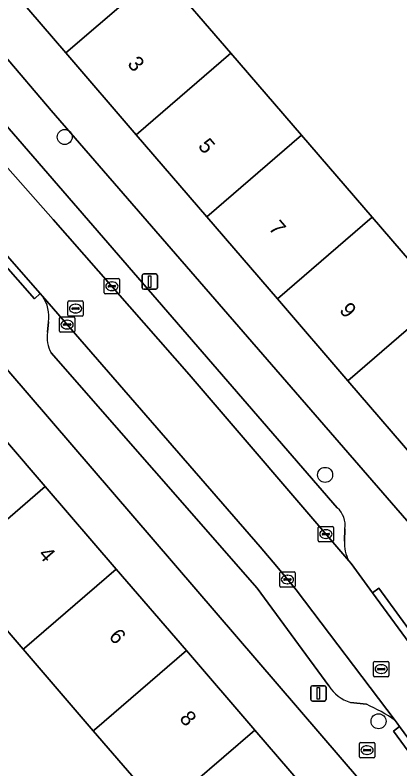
# Model space of a CAD drawing. Extents: x 162523 to 163266, y 381230 to 382050.
# Drawn here: x 162615.3 to 162640.34, y 381818.68 to 381867.74 of the extents above; entities that cross this region are included whole.
import ezdxf

# ---------------------------------------------------------------- set-up
doc = ezdxf.new("R2010")
doc.units = 0
for name, color, linetype in [('IMGEO_Boom', 7, 'Continuous'), ('IMGEO_Brandkraan', 7, 'Continuous'), ('IMGEO_Erf', 7, 'Continuous'), ('IMGEO_Kolk', 7, 'Continuous'), ('IMGEO_Lichtmast', 7, 'Continuous'), ('IMGEO_Pand', 7, 'Continuous'), ('IMGEO_Pand_nummerreeks', 7, 'Continuous'), ('IMGEO_Parkeervlak_open', 7, 'Continuous'), ('IMGEO_Rijbaan_lokaal_open', 7, 'Continuous'), ('IMGEO_Rioolput', 7, 'Continuous'), ('IMGEO_Voetpad_open', 7, 'Continuous')]:
    doc.layers.add(name, color=color, linetype=linetype)

msp = doc.modelspace()

# ---------------------------------------------------------------- linework, layer by layer
at = {"layer": 'IMGEO_Boom'}
for centre in [(162618.53, 381859.8), (162635.478, 381837.813), (162638.952, 381821.777)]:
    msp.add_circle(centre, 0.489, dxfattribs=at)
at = {"layer": 'IMGEO_Brandkraan'}
for p, q in [((162637.785, 381820.399), (162638.637, 381820.399)), ((162637.71, 381819.473), (162637.71, 381820.325)), ((162637.969, 381819.893), (162637.969, 381819.905)), ((162638.407, 381819.856), (162638.009, 381819.856)), ((162638.012, 381819.942), (162638.41, 381819.942)), ((162638.198, 381820.179), (162638.223, 381820.179)), ((162638.453, 381819.905), (162638.453, 381819.893)), ((162638.711, 381820.325), (162638.711, 381819.473)), ((162638.637, 381819.399), (162637.785, 381819.399)), ((162638.221, 381819.619), (162638.196, 381819.619))]:
    msp.add_line(p, q, dxfattribs=at)
for points in [[(162637.785, 381820.399), (162638.637, 381820.399)], [(162637.71, 381819.473), (162637.71, 381820.325)], [(162638.711, 381820.325), (162638.711, 381819.473)], [(162638.637, 381819.399), (162637.785, 381819.399)]]:
    msp.add_lwpolyline(points, dxfattribs=at)
for centre, radius, start, end in [((162637.787, 381820.323), 0.0765, 91.552, 178.448), ((162637.787, 381820.323), 0.0765, 91.552, 178.448), ((162638.635, 381820.323), 0.0765, 1.552, 88.448), ((162638.635, 381820.323), 0.0765, 1.552, 88.448), ((162638.009, 381819.902), 0.0403, 85.8775, 175.7526), ((162638.006, 381819.892), 0.0366, 178.938, 274.7102), ((162638.41, 381819.899), 0.043, 264.8664, 352.4533), ((162638.414, 381819.904), 0.0386, 1.7309, 96.639), ((162637.787, 381819.475), 0.0765, 181.552, 268.448), ((162637.787, 381819.475), 0.0765, 181.552, 268.448), ((162638.635, 381819.475), 0.0765, 271.552, 358.448), ((162638.635, 381819.475), 0.0765, 271.552, 358.448)]:
    msp.add_arc(centre, radius, start, end, dxfattribs=at)
for centre, major_axis, ratio, start_param, end_param in [((162638.197, 381819.899), (-0.387, 0.002), 0.722429, 4.712389, 7.853982), ((162638.222, 381819.899), (-0.39, 0.002), 0.717154, 1.570796, 4.712389)]:
    msp.add_ellipse(centre, major_axis=major_axis, ratio=ratio, start_param=start_param, end_param=end_param, dxfattribs=at)
at = {"layer": 'IMGEO_Erf'}
for points in [[(162608.447, 381872.351), (162617.656, 381861.527), (162641.079, 381834.52), (162645.193, 381837.891), (162645.564, 381838.195), (162651.746, 381843.259), (162654.733, 381845.707), (162655.225, 381846.11), (162652.994, 381848.812), (162648.983, 381853.709), (162649.512, 381854.143), (162647.831, 381856.195), (162645.254, 381859.341), (162647.405, 381861.103), (162649.938, 381858.01), (162651.663, 381855.904), (162655.674, 381851.007), (162656.106, 381851.292), (162641.659, 381868.486)], [(162624.758, 381870.581), (162629.348, 381865.247), (162633.94, 381859.912), (162638.532, 381854.575), (162642.976, 381849.413), (162643.125, 381849.24), (162646.224, 381851.908), (162648.431, 381849.344), (162645.33, 381846.676), (162647.663, 381843.965), (162648.065, 381843.499), (162647.74, 381843.22), (162647.361, 381843.661), (162643.626, 381840.446), (162641.872, 381838.937), (162642.27, 381838.474), (162641.918, 381838.171), (162636.961, 381843.931), (162632.368, 381849.268), (162627.776, 381854.603), (162623.185, 381859.939), (162618.592, 381865.275), (162613.633, 381871.038)], [(162637.769, 381817.908), (162613.536, 381846.073), (162608.946, 381841.96), (162607.949, 381841.067), (162606.255, 381839.549), (162604.298, 381841.733), (162605.992, 381843.251), (162606.989, 381844.144), (162606.643, 381844.53), (162611.397, 381848.79), (162607.795, 381852.831), (162606.311, 381854.495), (162602.884, 381851.424), (162601.7, 381850.363), (162597.214, 381846.343), (162592.736, 381842.329), (162588.257, 381838.316), (162583.779, 381834.303), (162579.309, 381830.297)], [(162615.822, 381826.466), (162611.203, 381831.833), (162606.117, 381837.742), (162606.445, 381838.024), (162606.802, 381837.609), (162608.744, 381839.28), (162612.249, 381842.296), (162611.907, 381842.694), (162612.192, 381842.939), (162617.262, 381837.048), (162621.883, 381831.678), (162626.444, 381826.379), (162630.902, 381821.198), (162635.455, 381815.908)], [(162624.843, 381815.984), (162620.382, 381821.167), (162615.822, 381826.466)]]:
    msp.add_lwpolyline(points, dxfattribs=at)
at = {"layer": 'IMGEO_Kolk'}
for p, q in [((162621.095, 381849.666), (162621.095, 381850.518)), ((162621.17, 381850.592), (162622.022, 381850.592)), ((162621.583, 381850.372), (162621.608, 381850.372)), ((162622.096, 381850.518), (162622.096, 381849.666)), ((162621.354, 381850.086), (162621.354, 381850.098)), ((162621.792, 381850.049), (162621.394, 381850.049)), ((162621.397, 381850.135), (162621.795, 381850.135)), ((162621.606, 381849.812), (162621.581, 381849.812)), ((162621.838, 381850.098), (162621.838, 381850.086)), ((162622.022, 381849.592), (162621.17, 381849.592)), ((162618.184, 381847.165), (162618.184, 381848.017)), ((162618.259, 381848.091), (162619.111, 381848.091)), ((162618.672, 381847.871), (162618.697, 381847.871)), ((162619.185, 381848.017), (162619.185, 381847.165)), ((162618.443, 381847.585), (162618.443, 381847.597)), ((162618.881, 381847.548), (162618.483, 381847.548)), ((162618.486, 381847.634), (162618.884, 381847.634)), ((162618.695, 381847.311), (162618.67, 381847.311)), ((162618.927, 381847.597), (162618.927, 381847.585)), ((162619.111, 381847.091), (162618.259, 381847.091)), ((162635.027, 381833.533), (162635.027, 381834.385)), ((162635.102, 381834.459), (162635.954, 381834.459)), ((162635.515, 381834.239), (162635.54, 381834.239)), ((162636.028, 381834.385), (162636.028, 381833.533)), ((162635.286, 381833.953), (162635.286, 381833.965)), ((162635.724, 381833.916), (162635.326, 381833.916)), ((162635.329, 381834.002), (162635.727, 381834.002)), ((162635.538, 381833.679), (162635.513, 381833.679)), ((162635.77, 381833.965), (162635.77, 381833.953)), ((162635.954, 381833.459), (162635.102, 381833.459)), ((162632.526, 381830.578), (162632.526, 381831.43)), ((162632.601, 381831.504), (162633.453, 381831.504)), ((162633.014, 381831.284), (162633.039, 381831.284)), ((162633.527, 381831.43), (162633.527, 381830.578)), ((162632.785, 381830.998), (162632.785, 381831.01)), ((162633.223, 381830.961), (162632.825, 381830.961)), ((162632.828, 381831.047), (162633.226, 381831.047)), ((162633.037, 381830.724), (162633.012, 381830.724)), ((162633.269, 381831.01), (162633.269, 381830.998)), ((162633.453, 381830.504), (162632.601, 381830.504))]:
    msp.add_line(p, q, dxfattribs=at)
for points in [[(162621.095, 381849.666), (162621.095, 381850.518)], [(162621.17, 381850.592), (162622.022, 381850.592)], [(162622.096, 381850.518), (162622.096, 381849.666)], [(162622.022, 381849.592), (162621.17, 381849.592)], [(162618.184, 381847.165), (162618.184, 381848.017)], [(162618.259, 381848.091), (162619.111, 381848.091)], [(162619.185, 381848.017), (162619.185, 381847.165)], [(162619.111, 381847.091), (162618.259, 381847.091)], [(162635.027, 381833.533), (162635.027, 381834.385)], [(162635.102, 381834.459), (162635.954, 381834.459)], [(162636.028, 381834.385), (162636.028, 381833.533)], [(162635.954, 381833.459), (162635.102, 381833.459)], [(162632.526, 381830.578), (162632.526, 381831.43)], [(162632.601, 381831.504), (162633.453, 381831.504)], [(162633.527, 381831.43), (162633.527, 381830.578)], [(162633.453, 381830.504), (162632.601, 381830.504)]]:
    msp.add_lwpolyline(points, dxfattribs=at)
for centre, radius, start, end in [((162621.172, 381850.516), 0.0765, 91.552, 178.448), ((162621.172, 381850.516), 0.0765, 91.552, 178.448), ((162622.02, 381850.516), 0.0765, 1.552, 88.448), ((162622.02, 381850.516), 0.0765, 1.552, 88.448), ((162621.394, 381850.095), 0.0403, 85.8775, 175.7526), ((162621.391, 381850.085), 0.0366, 178.938, 274.7102), ((162621.795, 381850.092), 0.043, 264.8664, 352.4533), ((162621.799, 381850.097), 0.0386, 1.7309, 96.639), ((162621.172, 381849.668), 0.0765, 181.552, 268.448), ((162621.172, 381849.668), 0.0765, 181.552, 268.448), ((162622.02, 381849.668), 0.0765, 271.552, 358.448), ((162622.02, 381849.668), 0.0765, 271.552, 358.448), ((162618.261, 381848.015), 0.0765, 91.552, 178.448), ((162618.261, 381848.015), 0.0765, 91.552, 178.448), ((162619.109, 381848.015), 0.0765, 1.552, 88.448), ((162619.109, 381848.015), 0.0765, 1.552, 88.448), ((162618.483, 381847.594), 0.0403, 85.8775, 175.7526), ((162618.48, 381847.584), 0.0366, 178.938, 274.7102), ((162618.884, 381847.591), 0.043, 264.8664, 352.4533), ((162618.888, 381847.596), 0.0386, 1.7309, 96.639), ((162618.261, 381847.167), 0.0765, 181.552, 268.448), ((162618.261, 381847.167), 0.0765, 181.552, 268.448), ((162619.109, 381847.167), 0.0765, 271.552, 358.448), ((162619.109, 381847.167), 0.0765, 271.552, 358.448), ((162635.104, 381834.383), 0.0765, 91.552, 178.448), ((162635.104, 381834.383), 0.0765, 91.552, 178.448), ((162635.952, 381834.383), 0.0765, 1.552, 88.448), ((162635.952, 381834.383), 0.0765, 1.552, 88.448), ((162635.326, 381833.962), 0.0403, 85.8775, 175.7526), ((162635.323, 381833.952), 0.0366, 178.938, 274.7102), ((162635.727, 381833.959), 0.043, 264.8664, 352.4533), ((162635.731, 381833.964), 0.0386, 1.7309, 96.639), ((162635.104, 381833.535), 0.0765, 181.552, 268.448), ((162635.104, 381833.535), 0.0765, 181.552, 268.448), ((162635.952, 381833.535), 0.0765, 271.552, 358.448), ((162635.952, 381833.535), 0.0765, 271.552, 358.448), ((162632.603, 381831.428), 0.0765, 91.552, 178.448), ((162632.603, 381831.428), 0.0765, 91.552, 178.448), ((162633.451, 381831.428), 0.0765, 1.552, 88.448), ((162633.451, 381831.428), 0.0765, 1.552, 88.448), ((162632.825, 381831.007), 0.0403, 85.8775, 175.7526), ((162632.822, 381830.997), 0.0366, 178.938, 274.7102), ((162633.226, 381831.004), 0.043, 264.8664, 352.4533), ((162633.23, 381831.009), 0.0386, 1.7309, 96.639), ((162632.603, 381830.58), 0.0765, 181.552, 268.448), ((162632.603, 381830.58), 0.0765, 181.552, 268.448), ((162633.451, 381830.58), 0.0765, 271.552, 358.448), ((162633.451, 381830.58), 0.0765, 271.552, 358.448)]:
    msp.add_arc(centre, radius, start, end, dxfattribs=at)
for centre, major_axis, ratio, start_param, end_param in [((162621.582, 381850.092), (-0.387, 0.002), 0.722429, 4.712389, 7.853982), ((162621.607, 381850.092), (-0.39, 0.002), 0.717154, 1.570796, 4.712389), ((162618.671, 381847.591), (-0.387, 0.002), 0.722429, 4.712389, 7.853982), ((162618.696, 381847.591), (-0.39, 0.002), 0.717154, 1.570796, 4.712389), ((162635.514, 381833.959), (-0.387, 0.002), 0.722429, 4.712389, 7.853982), ((162635.539, 381833.959), (-0.39, 0.002), 0.717154, 1.570796, 4.712389), ((162633.013, 381831.004), (-0.387, 0.002), 0.722429, 4.712389, 7.853982), ((162633.038, 381831.004), (-0.39, 0.002), 0.717154, 1.570796, 4.712389)]:
    msp.add_ellipse(centre, major_axis=major_axis, ratio=ratio, start_param=start_param, end_param=end_param, dxfattribs=at)
at = {"layer": 'IMGEO_Lichtmast'}
for p, q in [((162623.567, 381849.988), (162623.567, 381850.788)), ((162623.567, 381850.788), (162623.567, 381849.988)), ((162623.667, 381850.888), (162624.457, 381850.888)), ((162624.457, 381850.888), (162623.667, 381850.888)), ((162624.557, 381850.788), (162624.557, 381849.988)), ((162624.557, 381849.988), (162624.557, 381850.788)), ((162624.457, 381849.888), (162623.667, 381849.888)), ((162623.667, 381849.888), (162624.457, 381849.888)), ((162634.546, 381823.195), (162634.546, 381823.995)), ((162634.546, 381823.995), (162634.546, 381823.195)), ((162634.646, 381824.095), (162635.436, 381824.095)), ((162635.436, 381824.095), (162634.646, 381824.095)), ((162635.536, 381823.995), (162635.536, 381823.195)), ((162635.536, 381823.195), (162635.536, 381823.995)), ((162635.436, 381823.095), (162634.646, 381823.095)), ((162634.646, 381823.095), (162635.436, 381823.095))]:
    msp.add_line(p, q, dxfattribs=at)
for points in [[(162623.987, 381850.763), (162624.137, 381850.763), (162624.137, 381850.013), (162623.987, 381850.013), (162623.987, 381850.763)], [(162634.966, 381823.97), (162635.116, 381823.97), (162635.116, 381823.22), (162634.966, 381823.22), (162634.966, 381823.97)]]:
    msp.add_lwpolyline(points, dxfattribs=at)
for centre, start, end in [((162623.667, 381850.788), 90, 180), ((162623.667, 381850.788), 90, 180), ((162624.457, 381850.788), 0, 90), ((162624.457, 381850.788), 360, 90), ((162623.667, 381849.988), 180, 270), ((162623.667, 381849.988), 180, 270), ((162624.457, 381849.988), 270, 0), ((162624.457, 381849.988), 270, 0), ((162634.646, 381823.995), 90, 180), ((162634.646, 381823.995), 90, 180), ((162635.436, 381823.995), 0, 90), ((162635.436, 381823.995), 360, 90), ((162634.646, 381823.195), 180, 270), ((162634.646, 381823.195), 180, 270), ((162635.436, 381823.195), 270, 0), ((162635.436, 381823.195), 270, 0)]:
    msp.add_arc(centre, 0.1, start, end, dxfattribs=at)
at = {"layer": 'IMGEO_Pand'}
for points in [[(162620.098, 381875.995), (162619.79, 381876.353), (162619.382, 381876.003), (162619.691, 381875.644), (162614.191, 381870.91), (162613.89, 381871.259), (162613.633, 381871.038), (162618.592, 381865.275), (162624.758, 381870.581), (162622.482, 381873.226), (162625.435, 381875.769), (162623.052, 381878.537)], [(162623.185, 381859.939), (162629.348, 381865.247), (162624.758, 381870.581), (162618.592, 381865.275)], [(162627.776, 381854.603), (162633.94, 381859.912), (162629.348, 381865.247), (162623.185, 381859.939)], [(162627.776, 381854.603), (162632.368, 381849.268), (162638.532, 381854.575), (162633.94, 381859.912)], [(162638.532, 381854.575), (162632.368, 381849.268), (162636.961, 381843.931), (162643.125, 381849.24), (162642.976, 381849.413)], [(162647.663, 381843.965), (162645.33, 381846.676), (162648.431, 381849.344), (162646.224, 381851.908), (162643.125, 381849.24), (162636.961, 381843.931), (162641.918, 381838.171), (162642.27, 381838.474), (162641.872, 381838.937), (162643.626, 381840.446), (162647.361, 381843.661), (162647.74, 381843.22), (162648.065, 381843.499)], [(162611.203, 381831.833), (162617.262, 381837.048), (162612.192, 381842.939), (162611.907, 381842.694), (162612.249, 381842.296), (162608.744, 381839.28), (162606.802, 381837.609), (162606.445, 381838.024), (162606.117, 381837.742)], [(162621.883, 381831.678), (162617.262, 381837.048), (162611.203, 381831.833), (162615.822, 381826.466), (162615.918, 381826.544)], [(162621.883, 381831.678), (162615.918, 381826.544), (162615.822, 381826.466), (162620.382, 381821.167), (162620.463, 381821.232), (162626.444, 381826.379)], [(162626.444, 381826.379), (162620.463, 381821.232), (162620.382, 381821.167), (162624.843, 381815.984), (162630.902, 381821.198)], [(162630.902, 381821.198), (162624.843, 381815.984), (162626.551, 381813.999), (162629.442, 381810.639), (162629.812, 381810.209), (162630.118, 381810.472), (162629.742, 381810.908), (162635.229, 381815.63), (162635.572, 381815.231), (162635.84, 381815.461), (162635.455, 381815.908)]]:
    msp.add_lwpolyline(points, close=True, dxfattribs=at)
at = {"layer": 'IMGEO_Parkeervlak_open'}
for points in [[(162607.82, 381865.771), (162609.566, 381863.752), (162610.879, 381862.225), (162617.781, 381854.439), (162626.638, 381844.343), (162637.013, 381832.223)], [(162636.267, 381835.667), (162612.246, 381863.392), (162611.019, 381864.806)], [(162640.035, 381821.827), (162633.584, 381830.334), (162632.331, 381831.841), (162631.239, 381833.128), (162617.086, 381849.434)], [(162617.468, 381847.777), (162617.416, 381847.104)], [(162617.644, 381845.758), (162631.045, 381830.44), (162635.723, 381824.077)], [(162636.735, 381833.496), (162636.761, 381834.308)], [(162637.118, 381822.997), (162638.171, 381822.882)]]:
    msp.add_lwpolyline(points, dxfattribs=at)
for centre, radius, start, end in [((162615.197, 381848.126), 2.297, 351.2591, 34.7049), ((162619.324, 381846.735), 1.944, 169.0553, 210.1729), ((162635.299, 381834.546), 1.482, 350.7677, 49.185), ((162639.271, 381833.383), 2.538, 177.4462, 207.1917), ((162637.985, 381825.558), 2.704, 213.2149, 251.2915), ((162634.15, 381813.604), 10.112, 54.4111, 66.5703)]:
    msp.add_arc(centre, radius, start, end, dxfattribs=at)
at = {"layer": 'IMGEO_Rijbaan_lokaal_open'}
msp.add_lwpolyline([(162614.774, 381852.067), (162616.934, 381849.61), (162617.086, 381849.434), (162631.239, 381833.128), (162632.331, 381831.841), (162633.584, 381830.334), (162640.035, 381821.827), (162640.168, 381821.652), (162640.326, 381821.437), (162643.092, 381817.657), (162646.081, 381819.844), (162643.084, 381823.959), (162638.563, 381830.136), (162637.168, 381832.042), (162637.013, 381832.223), (162626.638, 381844.343), (162617.781, 381854.439), (162610.879, 381862.225)], dxfattribs=at)
at = {"layer": 'IMGEO_Rioolput'}
for p, q in [((162618.737, 381848.21), (162618.737, 381849.062)), ((162618.812, 381849.136), (162619.664, 381849.136)), ((162619.225, 381848.916), (162619.25, 381848.916)), ((162619.738, 381849.062), (162619.738, 381848.21)), ((162618.996, 381848.63), (162618.996, 381848.642)), ((162619.434, 381848.593), (162619.036, 381848.593)), ((162619.039, 381848.679), (162619.437, 381848.679)), ((162619.248, 381848.356), (162619.223, 381848.356)), ((162619.48, 381848.642), (162619.48, 381848.63)), ((162619.664, 381848.136), (162618.812, 381848.136)), ((162638.63, 381824.75), (162638.63, 381825.602)), ((162638.705, 381825.676), (162639.557, 381825.676)), ((162639.118, 381825.456), (162639.143, 381825.456)), ((162639.631, 381825.602), (162639.631, 381824.75)), ((162638.889, 381825.17), (162638.889, 381825.182)), ((162639.327, 381825.133), (162638.929, 381825.133)), ((162638.932, 381825.219), (162639.33, 381825.219)), ((162639.141, 381824.896), (162639.116, 381824.896)), ((162639.373, 381825.182), (162639.373, 381825.17)), ((162639.557, 381824.676), (162638.705, 381824.676))]:
    msp.add_line(p, q, dxfattribs=at)
for points in [[(162618.737, 381848.21), (162618.737, 381849.062)], [(162618.812, 381849.136), (162619.664, 381849.136)], [(162619.738, 381849.062), (162619.738, 381848.21)], [(162619.664, 381848.136), (162618.812, 381848.136)], [(162638.63, 381824.75), (162638.63, 381825.602)], [(162638.705, 381825.676), (162639.557, 381825.676)], [(162639.631, 381825.602), (162639.631, 381824.75)], [(162639.557, 381824.676), (162638.705, 381824.676)]]:
    msp.add_lwpolyline(points, dxfattribs=at)
for centre, radius, start, end in [((162618.814, 381849.06), 0.0765, 91.552, 178.448), ((162618.814, 381849.06), 0.0765, 91.552, 178.448), ((162619.662, 381849.06), 0.0765, 1.552, 88.448), ((162619.662, 381849.06), 0.0765, 1.552, 88.448), ((162619.036, 381848.639), 0.0403, 85.8775, 175.7526), ((162619.033, 381848.629), 0.0366, 178.938, 274.7102), ((162619.437, 381848.636), 0.043, 264.8664, 352.4533), ((162619.441, 381848.641), 0.0386, 1.7309, 96.639), ((162618.814, 381848.212), 0.0765, 181.552, 268.448), ((162618.814, 381848.212), 0.0765, 181.552, 268.448), ((162619.662, 381848.212), 0.0765, 271.552, 358.448), ((162619.662, 381848.212), 0.0765, 271.552, 358.448), ((162638.707, 381825.6), 0.0765, 91.552, 178.448), ((162638.707, 381825.6), 0.0765, 91.552, 178.448), ((162639.555, 381825.6), 0.0765, 1.552, 88.448), ((162639.555, 381825.6), 0.0765, 1.552, 88.448), ((162638.707, 381824.752), 0.0765, 181.552, 268.448), ((162638.707, 381824.752), 0.0765, 181.552, 268.448), ((162638.929, 381825.179), 0.0403, 85.8775, 175.7526), ((162638.926, 381825.169), 0.0366, 178.938, 274.7102), ((162639.33, 381825.176), 0.043, 264.8664, 352.4533), ((162639.334, 381825.181), 0.0386, 1.7309, 96.639), ((162639.555, 381824.752), 0.0765, 271.552, 358.448), ((162639.555, 381824.752), 0.0765, 271.552, 358.448)]:
    msp.add_arc(centre, radius, start, end, dxfattribs=at)
for centre, major_axis, ratio, start_param, end_param in [((162619.224, 381848.636), (-0.387, 0.002), 0.722429, 4.712389, 7.853982), ((162619.249, 381848.636), (-0.39, 0.002), 0.717154, 1.570796, 4.712389), ((162639.117, 381825.176), (-0.387, 0.002), 0.722429, 4.712389, 7.853982), ((162639.142, 381825.176), (-0.39, 0.002), 0.717154, 1.570796, 4.712389)]:
    msp.add_ellipse(centre, major_axis=major_axis, ratio=ratio, start_param=start_param, end_param=end_param, dxfattribs=at)
at = {"layer": 'IMGEO_Voetpad_open'}
for points in [[(162646.757, 381824.316), (162646.101, 381827.394), (162642.953, 381831.956), (162641.079, 381834.52), (162617.656, 381861.527), (162608.447, 381872.351), (162604.976, 381869.467)], [(162601.273, 381866.45), (162597.983, 381863.68), (162600.585, 381860.822), (162600.945, 381861.145), (162601.189, 381860.873), (162600.816, 381860.539), (162606.001, 381854.753), (162606.34, 381855.058), (162606.607, 381854.76), (162606.311, 381854.495), (162607.795, 381852.831), (162611.397, 381848.79), (162613.7, 381846.22), (162613.536, 381846.073), (162637.769, 381817.908), (162641.055, 381814.077), (162691.781, 381755.909)], [(162611.019, 381864.806), (162612.246, 381863.392), (162636.267, 381835.667)], [(162617.086, 381849.434), (162616.934, 381849.61), (162616.561, 381849.279), (162614.401, 381851.736), (162614.774, 381852.067)], [(162617.416, 381847.104), (162617.468, 381847.777)], [(162635.723, 381824.077), (162631.045, 381830.44), (162617.644, 381845.758)], [(162636.761, 381834.308), (162636.735, 381833.496)], [(162637.013, 381832.223), (162637.168, 381832.042), (162638.563, 381830.136), (162638.966, 381830.431), (162643.487, 381824.254), (162643.084, 381823.959), (162646.081, 381819.844), (162647.554, 381817.822)], [(162638.171, 381822.882), (162637.118, 381822.997)], [(162639.923, 381821.142), (162640.326, 381821.437), (162640.168, 381821.652), (162640.035, 381821.827)], [(162645.988, 381813.796), (162645.795, 381814.018), (162645.551, 381814.298), (162645.167, 381814.823), (162644.181, 381816.17), (162643.843, 381816.631), (162643.44, 381816.336), (162639.923, 381821.142)]]:
    msp.add_lwpolyline(points, dxfattribs=at)
for points in [[(162614.774, 381852.067), (162614.401, 381851.736), (162616.561, 381849.279), (162616.934, 381849.61)], [(162643.084, 381823.959), (162643.487, 381824.254), (162638.966, 381830.431), (162638.563, 381830.136)], [(162640.326, 381821.437), (162639.923, 381821.142), (162643.44, 381816.336), (162643.843, 381816.631), (162643.404, 381817.231), (162643.092, 381817.657)]]:
    msp.add_lwpolyline(points, close=True, dxfattribs=at)
for centre, radius, start, end in [((162615.197, 381848.126), 2.297, 351.2591, 34.7049), ((162619.324, 381846.735), 1.944, 169.0553, 210.1729), ((162635.299, 381834.546), 1.482, 350.7677, 49.185), ((162639.271, 381833.383), 2.538, 177.4462, 207.1917), ((162637.985, 381825.558), 2.704, 213.2149, 251.2915), ((162634.15, 381813.604), 10.112, 54.4111, 66.5703)]:
    msp.add_arc(centre, radius, start, end, dxfattribs=at)

# ---------------------------------------------------------------- texts
at = {"layer": 'IMGEO_Pand_nummerreeks'}
for s, rotation, p in [('3', 310.7149, (162622.56, 381864.528)), ('5', 310.7149, (162627.158, 381859.185)), ('7', 310.7149, (162631.756, 381853.843)), ('9', 310.7142, (162636.354, 381848.5)), ('4', 310.7158, (162616.757, 381832.606)), ('6', 310.7158, (162621.349, 381827.27)), ('8', 310.7158, (162625.945, 381821.931))]:
    msp.add_text(s, height=1, rotation=rotation, dxfattribs=at).set_placement(p)

doc.saveas('drawing.dxf')
